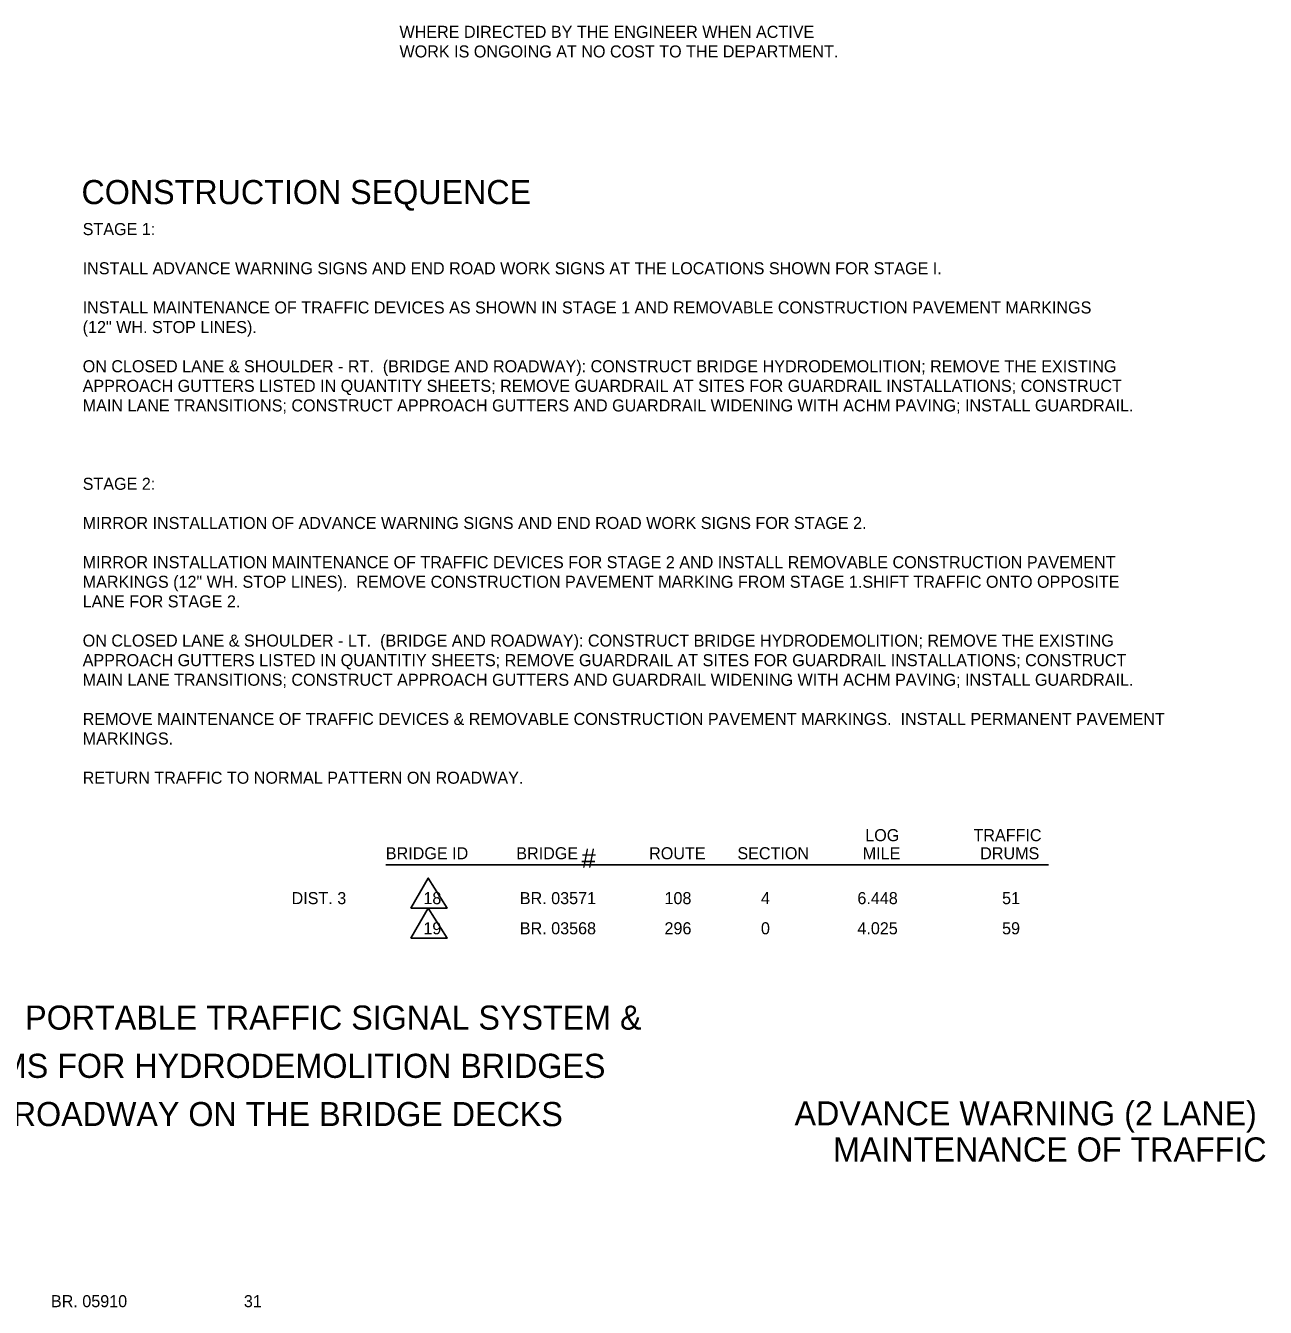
# Model space of a CAD drawing. Extents: x 1930579 to 1939784, y 596179 to 597522.
# Drawn here: x 1938290 to 1938907, y 596238 to 596876 of the extents above; entities that cross this region are included whole.
import ezdxf

# ---------------------------------------------------------------- set-up
doc = ezdxf.new("R2010")
doc.units = 0
doc.layers.add('Default', color=7, linetype='Continuous')
doc.layers.add('R_Annotation', color=7, linetype='Continuous')

msp = doc.modelspace()

# ---------------------------------------------------------------- linework, layer by layer
at = {"layer": 'R_Annotation'}
msp.add_line((1938468.89, 596458.38), (1938798.69, 596458.38), dxfattribs=at)
for points in [[(1938481.41, 596436.76), (1938499.37, 596436.76), (1938490.04, 596451.72)], [(1938481.41, 596421.76), (1938499.37, 596421.76), (1938490.04, 596436.72)]]:
    msp.add_lwpolyline(points, close=True, dxfattribs=at)

# ---------------------------------------------------------------- texts
at = {"layer": 'Default'}
for s, p in [('LANE CLOSURE WITH PORTABLE TRAFFIC SIGNAL SYSTEM &', (1938115.55, 596376.3)), ('TRAFFIC DRUMS FOR HYDRODEMOLITION BRIDGES', (1938169.88, 596352.3)), ("24' & 28' CLEAR ROADWAY ON THE BRIDGE DECKS", (1938159.39, 596328.3))]:
    msp.add_text(s, height=12, rotation=360, dxfattribs=at).set_placement(p)
at = {"layer": 'R_Annotation'}
for s, height, p in [('WHERE DIRECTED BY THE ENGINEER WHEN ACTIVE', 6, (1938475.69, 596869.8)), ('WORK IS ONGOING AT NO COST TO THE DEPARTMENT.', 6, (1938475.69, 596860.05)), ('CONSTRUCTION SEQUENCE', 12, (1938317.44, 596787.07)), ('STAGE 1:', 6, (1938318.04, 596771.66)), ('INSTALL ADVANCE WARNING SIGNS AND END ROAD WORK SIGNS AT THE LOCATIONS SHOWN FOR STAGE I.  ', 6, (1938318.04, 596752.16)), ('INSTALL MAINTENANCE OF TRAFFIC DEVICES AS SHOWN IN STAGE 1 AND REMOVABLE CONSTRUCTION PAVEMENT MARKINGS ', 6, (1938318.04, 596732.66)), ('(12" WH. STOP LINES). ', 6, (1938318.04, 596722.91)), ('ON CLOSED LANE & SHOULDER - RT.  (BRIDGE AND ROADWAY): CONSTRUCT BRIDGE HYDRODEMOLITION; REMOVE THE EXISTING ', 6, (1938318.04, 596703.41)), ('APPROACH GUTTERS LISTED IN QUANTITY SHEETS; REMOVE GUARDRAIL AT SITES FOR GUARDRAIL INSTALLATIONS; CONSTRUCT ', 6, (1938318.04, 596693.66)), ('MAIN LANE TRANSITIONS; CONSTRUCT APPROACH GUTTERS AND GUARDRAIL WIDENING WITH ACHM PAVING; INSTALL GUARDRAIL. ', 6, (1938318.04, 596683.91)), ('STAGE 2:', 6, (1938318.04, 596644.91)), ('MIRROR INSTALLATION OF ADVANCE WARNING SIGNS AND END ROAD WORK SIGNS FOR STAGE 2.  ', 6, (1938318.04, 596625.41)), ('MIRROR INSTALLATION MAINTENANCE OF TRAFFIC DEVICES FOR STAGE 2 AND INSTALL REMOVABLE CONSTRUCTION PAVEMENT ', 6, (1938318.04, 596605.91)), ('MARKINGS (12" WH. STOP LINES).  REMOVE CONSTRUCTION PAVEMENT MARKING FROM STAGE 1.SHIFT TRAFFIC ONTO OPPOSITE ', 6, (1938318.04, 596596.16)), ('LANE FOR STAGE 2.', 6, (1938318.04, 596586.41)), ('ON CLOSED LANE & SHOULDER - LT.  (BRIDGE AND ROADWAY): CONSTRUCT BRIDGE HYDRODEMOLITION; REMOVE THE EXISTING ', 6, (1938318.04, 596566.91)), ('APPROACH GUTTERS LISTED IN QUANTITIY SHEETS; REMOVE GUARDRAIL AT SITES FOR GUARDRAIL INSTALLATIONS; CONSTRUCT ', 6, (1938318.04, 596557.16)), ('MAIN LANE TRANSITIONS; CONSTRUCT APPROACH GUTTERS AND GUARDRAIL WIDENING WITH ACHM PAVING; INSTALL GUARDRAIL.', 6, (1938318.04, 596547.41)), ('REMOVE MAINTENANCE OF TRAFFIC DEVICES & REMOVABLE CONSTRUCTION PAVEMENT MARKINGS.  INSTALL PERMANENT PAVEMENT ', 6, (1938318.04, 596527.91)), ('MARKINGS.', 6, (1938318.04, 596518.16)), ('RETURN TRAFFIC TO NORMAL PATTERN ON ROADWAY. ', 6, (1938318.04, 596498.66)), ('LOG', 6, (1938707.48, 596470.08)), ('TRAFFIC', 6, (1938761.34, 596470.08)), ('BRIDGE ID', 6, (1938468.89, 596461.08)), ('BRIDGE ', 6, (1938533.83, 596461.08)), ('#', 9.6, (1938566.25, 596456.84)), ('ROUTE', 6, (1938599.93, 596461.08)), ('SECTION', 6, (1938643.86, 596461.08)), ('MILE', 6, (1938706.23, 596461.08)), ('DRUMS', 6, (1938764.67, 596461.08)), ('DIST. 3', 6, (1938422, 596438.74)), ('18', 6, (1938487.58, 596438.74)), ('BR. 03571', 6, (1938535.58, 596438.74)), ('108', 6, (1938607.58, 596438.74)), ('4', 6, (1938655.58, 596438.74)), ('6.448', 6, (1938703.58, 596438.74)), ('51', 6, (1938775.58, 596438.74)), ('19', 6, (1938487.58, 596423.74)), ('BR. 03568', 6, (1938535.58, 596423.74)), ('296', 6, (1938607.58, 596423.74)), ('0', 6, (1938655.58, 596423.74)), ('4.025', 6, (1938703.58, 596423.74)), ('59', 6, (1938775.58, 596423.74)), ('ADVANCE WARNING (2 LANE)', 12, (1938672.29, 596328.68)), ('MAINTENANCE OF TRAFFIC', 12, (1938691.47, 596310.68)), ('BR. 05910', 6, (1938302.25, 596238.2)), ('31', 6, (1938398.25, 596238.2))]:
    msp.add_text(s, height=height, rotation=360, dxfattribs=at).set_placement(p)

doc.saveas('drawing.dxf')
